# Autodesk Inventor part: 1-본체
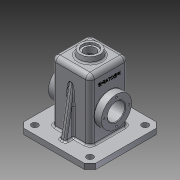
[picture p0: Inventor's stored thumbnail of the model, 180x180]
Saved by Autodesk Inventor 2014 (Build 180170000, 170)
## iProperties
Created: 2016-02
Part Number: 1-본체
Material: 알루미늄 6061
Document SubType Name: Modeling
Designer: 전형준
Density: 2.71 g/cm^3
Appearance: 알루미늄 - 평지
Mass: 932.812 g
Surface Area: 1043.48 cm^2
Volume: 344.211 cm^3
Author: 전형준
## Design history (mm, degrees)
sketch "스케치2"
  geometry: L1 (65, 65)-(-65, 65); L2 (-65, 65)-(-65, -65); L3 (-65, -65)-(65, -65); L4 (65, -65)-(65, 65); 3 further points
  constraints: 8 end point, 2 midpoint, 2 parallel, 1 horizontal, 1 horizontal alignment, 1 perpendicular, 1 vertical alignment
  dimensions: "d2" = 130 distance of L1.start L1.end; "d3" = 130 distance of L3.end L1.start
extrude "돌출1" new body sketch "스케치2" distance "d4" = 10; taper "d5" = 0 deg
sketch "스케치3"
  geometry: L1 (-35, 35)-(35, 35); L2 (35, 35)-(35, -35); L3 (35, -35)-(-35, -35); L4 (-35, -35)-(-35, 35); 3 further points
  constraints: 8 end point, 2 midpoint, 2 parallel, 1 horizontal, 1 horizontal alignment, 1 perpendicular, 1 vertical alignment
  dimensions: "d6" = 70 distance of L1.start L1.end; "d7" = 70 distance of L1.end L2.end (= d6)
extrude "돌출2" join sketch "스케치3" distance "d8" = 110; taper "d9" = 0 deg
feature "쉘1" dims "d10" = 10, "d11" = 5
fillet "모깎기1" dims "d12" = 8
fillet "모깎기2" dims "d13" = 8
chamfer "모따기1" distance "d14" = 10; stored, may be unused: second distance "d15" = 2, angle "d16" = 45 deg
fillet "모깎기3" dims "d17" = 3
fillet "모깎기4" dims "d18" = 3
sketch "스케치4"
  geometry: L1 (-55, -65)-(55, -65) reference; L2 (-65, 55)-(-65, -55) reference; 2 further points
  dimensions: "d19" = 15 distance from line of L1 point (-50, -50); "d20" = 15 distance from line of L2 point (-50, -50)
hole "구멍1" sketch "스케치4" at (-50, -50) diameter "d21" = 12; stored, may be unused: countersink angle "d25" = 90 deg, drill point angle "d27" = 118 deg; dims "d22" = 6, "d23" = 4, "d24" = 2, "d26" = 8
sketch "스케치5"
  geometry: C1 r 20 at (0, 0); 1 further point
  constraints: 1 centre point, 1 coincident
  dimensions: "d34" = 40 diameter of C1
extrude "돌출3" join sketch "스케치5" distance "d35" = 10; taper "d36" = -10 deg
fillet "모깎기5" dims "d37" = 3
hole "구멍2" diameter "d40" = 21; stored, may be unused: countersink angle "d44" = 90 deg, drill point angle "d46" = 118 deg; dims "d38" = 10, "d39" = 10, "d41" = 6, "d42" = 28, "d43" = 4, "d45" = 8
sketch "스케치6"
  geometry: L1 (10, -28)-(10, 82) reference; C1 r 27.5 at (-45, 27); 2 further points
  constraints: 1 centre point, 1 horizontal alignment, 1 midpoint
  dimensions: "d47" = 55 diameter of C1; "d48" = 55 distance from line of C1.centre L1
extrude "돌출4" join sketch "스케치6" distance "d49" = 13; taper "d50" = 0 deg
fillet "모깎기6" dims "d51" = 0.5
sketch "스케치9"
  geometry: C1 r 27.5 at (55, 27) reference; C2 r 27.5 at (55, 27); 1 further point
  constraints: 1 centre point, 1 coincident, 1 concentric
  dimensions: "d52" = 55 diameter of C2 (derived)
extrude "돌출5" join sketch "스케치9" distance "d53" = 7; taper "d54" = -45 deg
sketch "스케치10" dims "d55" = 45
  geometry: C1 r 27.5 at (0, 0) reference; 3 further points
  constraints: 2 vertical alignment, 1 coincident, 2 other
hole "구멍3" sketch "스케치10" at (0, 22.5) diameter "d56" = 3.242; stored, may be unused: countersink angle "d60" = 90 deg, drill point angle "d62" = 118 deg; dims "d57" = 8, "d58" = 28, "d59" = 4, "d61" = 10
hole "구멍4" diameter "d69" = 32; stored, may be unused: countersink angle "d73" = 90 deg, drill point angle "d75" = 0 deg; dims "d67" = 10, "d68" = 10, "d70" = 8, "d71" = 28, "d72" = 4, "d74" = 10
chamfer "모따기2" distance "d76" = 1; stored, may be unused: second distance "d77" = 2, angle "d78" = 45 deg
fillet "모깎기8" dims "d79" = 0.5
fillet "모깎기9" dims "d80" = 0.5
sketch "스케치11"
  geometry: L1 (65, 10)-(65, 0) reference; L2 (50, 10)-(50, 0); L3 (50, 10)-(35, 95.069); L4 (35, 112)-(35, 10) reference; L5 (44, 10)-(56, 10) reference; L6 (55, 10)-(65, 10) reference; L7 (55, 10)-(-55, 10) reference; 1 further point
  constraints: 4 end point, 1 midpoint, 1 parallel, 1 point on line
  dimensions: "d81" = 15 distance between parallel lines of L2 L1; "d82" = 10 deg angle of L3 L2
feature "리브1" sketch "스케치11" dims "d83" = 1, "d84" = 10, "d85" = 0, "d86" = 0, "d87" = 1, "d88" = 1
fillet "모깎기15" dims "d94" = 3
fillet "모깎기16" dims "d95" = 3
fillet "모깎기17" dims "d96" = 3
sketch "스케치12"
  geometry: L1 (5.57, 6.261)-(5.57, 47.739); L2 (5.57, 47.739)-(18.43, 47.739); L3 (18.43, 47.739)-(18.43, 6.261); L4 (18.43, 6.261)-(5.57, 6.261); L5 (112, -28)-(112, 82) reference; L6 (-18, 8.763)-(-18, 45.237) reference; L7 (0, -8)-(99, -8) reference; 5 further points
  constraints: 3 midpoint, 2 horizontal alignment, 1 parallel, 1 vertical alignment, 2 other
  dimensions: "d97" = 30 distance from line of point (12, 27) L6; "d98" = 35 distance from line of L7 point (12, 27) (derived)
feature "엠보싱1" sketch "스케치12" dims "d2" = 130, "d3" = 130, "d12" = 8, "d99" = 0.5, "d100" = 0
node "솔리드1"
pattern_linear "직사각형 패턴1" dims "d30" = 100
pattern_circular "원형 패턴1" dims angle "d64" = 360 deg
mirror "대칭2"
mirror "대칭3"
node "투영된 루프1"
